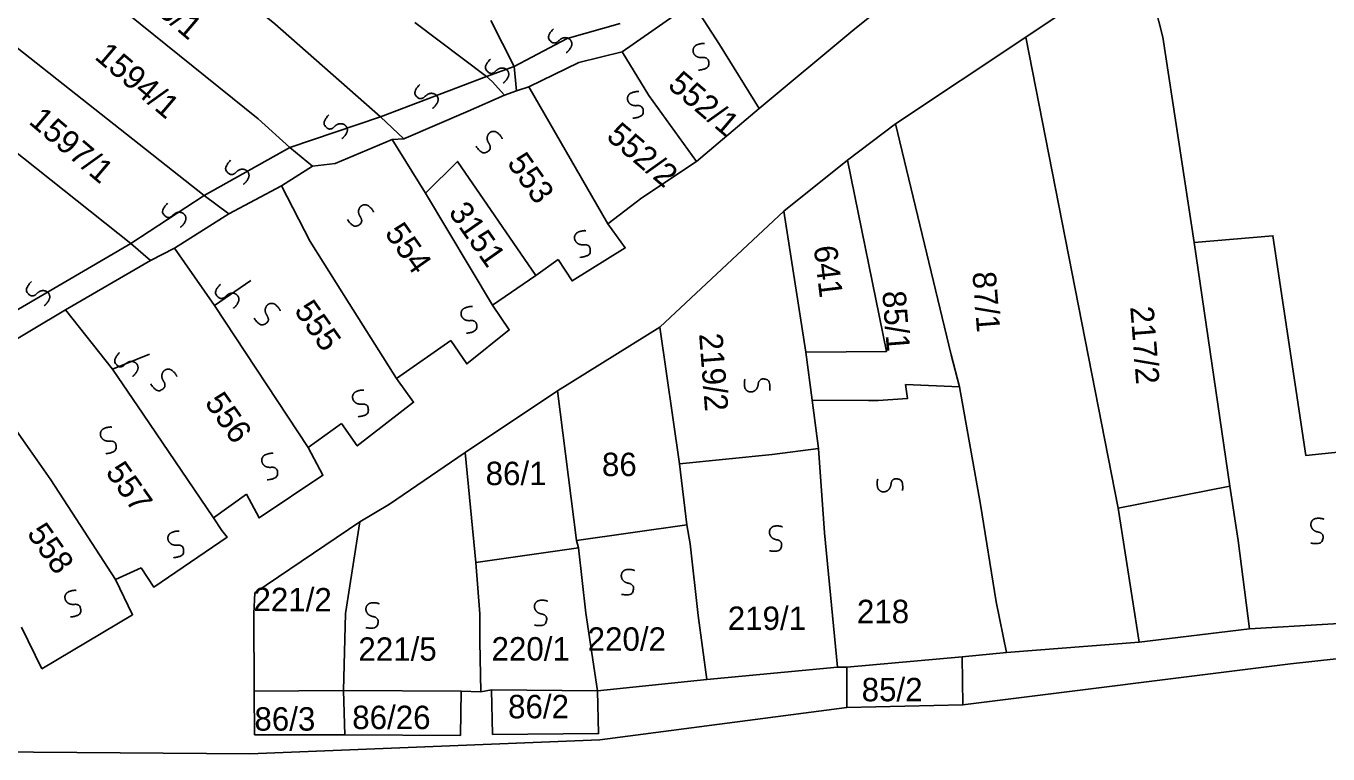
# Model space of a CAD drawing. Extents: x -581999 to -572728, y -1219553 to -1212032.
# Drawn here: x -578042.6 to -577931.4, y -1215726.9 to -1215664.7 of the extents above; entities that cross this region are included whole.
import ezdxf

# ---------------------------------------------------------------- set-up
doc = ezdxf.new("R2010")
doc.units = 0
for name, color, linetype in [('Vrstva 1', 7, 'Continuous'), ('Vrstva 2', 7, 'Continuous'), ('Vrstva 4', 7, 'Continuous'), ('Vrstva 6', 7, 'Continuous')]:
    doc.layers.add(name, color=color, linetype=linetype)

msp = doc.modelspace()

# ---------------------------------------------------------------- linework, layer by layer
at = {"layer": 'Vrstva 1'}
for p, q in [((-578000.916, -1215668.166), (-578002.908, -1215664.238)), ((-578009.426, -1215664.406), (-578003.287, -1215669.031)), ((-578000.724, -1215670.267), (-578000.916, -1215668.166)), ((-578003.287, -1215669.031), (-578002.816, -1215669.453)), ((-578002.816, -1215669.453), (-578001.768, -1215670.63)), ((-578001.768, -1215670.63), (-578000.724, -1215670.267)), ((-578000.724, -1215670.267), (-577999.68, -1215669.905)), ((-578011.58, -1215705.586), (-578014.107, -1215707.078)), ((-578015.499, -1215721.494), (-578023.147, -1215721.566)), ((-578005.509, -1215725.357), (-578005.466, -1215721.56))]:
    msp.add_line(p, q, dxfattribs=at)
for points in [[(-578010.347, -1215674.345), (-578012.339, -1215672.49), (-578021.393, -1215664.534), (-578035.16, -1215653.349)], [(-577962.568, -1215657.531), (-577971.99, -1215665.112)], [(-578039.598, -1215659.101), (-578022.818, -1215672.639), (-578020.097, -1215675.084), (-578018.175, -1215676.685)], [(-577947.207, -1215658.946), (-577957.198, -1215665.671)], [(-577945.486, -1215665.678), (-577947.207, -1215658.946)], [(-577991.691, -1215666.918), (-577985.695, -1215662.736)], [(-577983.381, -1215666.283), (-577985.695, -1215662.736)], [(-577979.987, -1215671.753), (-577971.99, -1215665.112)], [(-578044.482, -1215665.732), (-578027.425, -1215679.191), (-578025.299, -1215680.776)], [(-577979.987, -1215671.753), (-577983.381, -1215666.283)], [(-577957.198, -1215665.671), (-577968.344, -1215673.088)], [(-577949.308, -1215705.915), (-577957.198, -1215665.671)], [(-577942.813, -1215683.203), (-577945.486, -1215665.678)], [(-577995.412, -1215667.819), (-577991.691, -1215666.918)], [(-577989.416, -1215670.654), (-577991.691, -1215666.918)], [(-577999.68, -1215669.905), (-577995.412, -1215667.819)], [(-578004.855, -1215671.989), (-578001.768, -1215670.63)], [(-577992.91, -1215681.615), (-577999.68, -1215669.905)], [(-577985.349, -1215676.302), (-577989.416, -1215670.654)], [(-578032, -1215684.75), (-578033.675, -1215683.298), (-578048.595, -1215671.467)], [(-578010.347, -1215674.345), (-578004.855, -1215671.989)], [(-577985.349, -1215676.302), (-577979.987, -1215671.753)], [(-577968.344, -1215673.088), (-577972.433, -1215676.18)], [(-577963.579, -1215692.812), (-577968.344, -1215673.088)], [(-578016.228, -1215676.473), (-578011.355, -1215674.419)], [(-578011.355, -1215674.419), (-578010.347, -1215674.345)], [(-578008.5, -1215679.005), (-578011.355, -1215674.419)], [(-578018.175, -1215676.685), (-578016.228, -1215676.473)], [(-577999.067, -1215686.03), (-578005.782, -1215676.282), (-578008.5, -1215679.005)], [(-577990.023, -1215679.406), (-577985.349, -1215676.302)], [(-577972.433, -1215676.18), (-577977.884, -1215680.547)], [(-577976, -1215692.59), (-577969.108, -1215692.52), (-577972.433, -1215676.18)], [(-578018.175, -1215676.685), (-578020.806, -1215678.374)], [(-578020.806, -1215678.374), (-578025.299, -1215680.776)], [(-578018.367, -1215683.132), (-578020.806, -1215678.374)], [(-578002.791, -1215688.575), (-578008.5, -1215679.005)], [(-577992.91, -1215681.615), (-577990.023, -1215679.406)], [(-578029.957, -1215683.702), (-578025.299, -1215680.776)], [(-577977.884, -1215680.547), (-577988.492, -1215690.448)], [(-577976, -1215692.59), (-577977.884, -1215680.547)], [(-577997.158, -1215684.666), (-577995.983, -1215686.496), (-577991.442, -1215683.679), (-577992.91, -1215681.615)], [(-578015.023, -1215688.439), (-578018.367, -1215683.132)], [(-577939.786, -1215704.027), (-577942.813, -1215683.203)], [(-578032, -1215684.75), (-578029.957, -1215683.702)], [(-578026.544, -1215688.586), (-578029.957, -1215683.702)], [(-578039.258, -1215688.975), (-578032, -1215684.75)], [(-577999.067, -1215686.03), (-577997.158, -1215684.666)], [(-578002.791, -1215688.575), (-577999.067, -1215686.03)], [(-578018.542, -1215700.734), (-578026.544, -1215688.586)], [(-578010.969, -1215694.85), (-578015.023, -1215688.439)], [(-578006.335, -1215691.578), (-578004.979, -1215693.591), (-578001.344, -1215690.68), (-578002.791, -1215688.575)], [(-578045.109, -1215692.441), (-578039.258, -1215688.975)], [(-578035.266, -1215694.038), (-578039.258, -1215688.975)], [(-577988.492, -1215690.448), (-577997.211, -1215695.899)], [(-577986.792, -1215702.127), (-577988.492, -1215690.448)], [(-578010.969, -1215694.85), (-578006.335, -1215691.578)], [(-577975.466, -1215696.701), (-577976, -1215692.59)], [(-577962.86, -1215695.553), (-577963.579, -1215692.812)], [(-578042.318, -1215700.935), (-578047.168, -1215694.068)], [(-578032.643, -1215697.882), (-578035.266, -1215694.038)], [(-578015.694, -1215698.671), (-578014.338, -1215700.593), (-578009.522, -1215696.864), (-578010.969, -1215694.85)], [(-577962.86, -1215695.553), (-577967.483, -1215695.356), (-577967.306, -1215696.544), (-577969.827, -1215696.727), (-577970.244, -1215696.721)], [(-577997.211, -1215695.899), (-578005.115, -1215701.171)], [(-577995.605, -1215708.674), (-577997.211, -1215695.899)], [(-577961.073, -1215705.601), (-577962.86, -1215695.553)], [(-577974.932, -1215700.81), (-577975.466, -1215696.701)], [(-577970.244, -1215696.721), (-577970.66, -1215696.716), (-577975.466, -1215696.701)], [(-578026.629, -1215706.737), (-578032.643, -1215697.882)], [(-578018.542, -1215700.734), (-578015.694, -1215698.671)], [(-578038.343, -1215706.828), (-578040.509, -1215703.499), (-578042.318, -1215700.935)], [(-578023.813, -1215704.736), (-578022.729, -1215706.749), (-578017.278, -1215703.112), (-578018.542, -1215700.734)], [(-577978.87, -1215701.321), (-577974.932, -1215700.81)], [(-577974.406, -1215708.025), (-577974.932, -1215700.81)], [(-578005.115, -1215701.171), (-578011.58, -1215705.586)], [(-578004.213, -1215710.567), (-578005.115, -1215701.171)], [(-577986.792, -1215702.127), (-577978.87, -1215701.321)], [(-577986.171, -1215707.333), (-577986.792, -1215702.127)], [(-577949.308, -1215705.915), (-577939.786, -1215704.027)], [(-577939.074, -1215708.685), (-577939.786, -1215704.027)], [(-578026.629, -1215706.737), (-578023.813, -1215704.736)], [(-577959.734, -1215713.913), (-577961.073, -1215705.601)], [(-577947.517, -1215717.383), (-577949.308, -1215705.915)], [(-578034.986, -1215712.007), (-578038.343, -1215706.828)], [(-578032.808, -1215711.009), (-578031.723, -1215712.656), (-578025.453, -1215708.384), (-578025.906, -1215707.834), (-578026.629, -1215706.737)], [(-578014.107, -1215707.078), (-578023.101, -1215713.168), (-578023.187, -1215714.908)], [(-578014.107, -1215707.078), (-578015.337, -1215714.932)], [(-577986.171, -1215707.333), (-577995.605, -1215708.674)], [(-577985.902, -1215708.978), (-577986.171, -1215707.333)], [(-577995.605, -1215708.674), (-577995.425, -1215709.313)], [(-577973.308, -1215719.495), (-577974.406, -1215708.025)], [(-577938.087, -1215716.225), (-577939.074, -1215708.685)], [(-578004.213, -1215710.567), (-577995.425, -1215709.313)], [(-577995.425, -1215709.313), (-577995.114, -1215712.099)], [(-577985.191, -1215715.096), (-577985.902, -1215708.978)], [(-578034.986, -1215712.007), (-578032.808, -1215711.009)], [(-578003.861, -1215714.95), (-578004.213, -1215710.567)], [(-578041.283, -1215719.648), (-578033.542, -1215715.025), (-578034.986, -1215712.007)], [(-577995.114, -1215712.099), (-577994.803, -1215714.884)], [(-577958.849, -1215718.261), (-577959.734, -1215713.913)], [(-578023.187, -1215714.908), (-578023.147, -1215721.566), (-578023.105, -1215725.279)], [(-578015.499, -1215721.494), (-578015.337, -1215714.932)], [(-578003.785, -1215721.615), (-578003.856, -1215717.327), (-578003.861, -1215714.95)], [(-577994.803, -1215714.884), (-577993.803, -1215721.533)], [(-577984.462, -1215720.557), (-577985.191, -1215715.096)], [(-577938.087, -1215716.225), (-577924.713, -1215715.444), (-577913.836, -1215714.565)], [(-578043.041, -1215716.088), (-578041.283, -1215719.648)], [(-577947.517, -1215717.383), (-577938.087, -1215716.225)], [(-577962.577, -1215722.723), (-577934.59, -1215719.212), (-577918.452, -1215717.442)], [(-577958.849, -1215718.261), (-577947.517, -1215717.383)], [(-578126.538, -1215718.24), (-578119.18, -1215721.907), (-578097.504, -1215726.345), (-578023.529, -1215726.924)], [(-577962.658, -1215718.615), (-577972.491, -1215719.498)], [(-577962.658, -1215718.615), (-577958.849, -1215718.261)], [(-577962.577, -1215722.723), (-577962.658, -1215718.615)], [(-577984.462, -1215720.557), (-577973.308, -1215719.495)], [(-577973.308, -1215719.495), (-577972.491, -1215719.498)], [(-577972.491, -1215719.498), (-577972.5, -1215722.966)], [(-577993.803, -1215721.533), (-577984.462, -1215720.557)], [(-578015.395, -1215725.302), (-578015.499, -1215721.494)], [(-578015.499, -1215721.494), (-578005.466, -1215721.56)], [(-578005.466, -1215721.56), (-578003.785, -1215721.615)], [(-578002.878, -1215721.435), (-578003.785, -1215721.615)], [(-578002.789, -1215725.248), (-578002.878, -1215721.435)], [(-577993.803, -1215721.533), (-578002.878, -1215721.435)], [(-578002.789, -1215725.248), (-577993.721, -1215725.184), (-577993.803, -1215721.533)], [(-578023.529, -1215726.924), (-577993.614, -1215725.708), (-577972.5, -1215722.966)], [(-577972.5, -1215722.966), (-577962.577, -1215722.723)], [(-578023.105, -1215725.279), (-578015.395, -1215725.302)], [(-578015.395, -1215725.302), (-578005.509, -1215725.357)]]:
    msp.add_lwpolyline(points, dxfattribs=at)
at = {"layer": 'Vrstva 4'}
for p, q in [((-577996.39, -1215665.788), (-577991.864, -1215664.491)), ((-578000.916, -1215668.166), (-577996.39, -1215665.788)), ((-578003.287, -1215669.031), (-578000.916, -1215668.166)), ((-578012.339, -1215672.49), (-578003.287, -1215669.031)), ((-578020.097, -1215675.084), (-578012.339, -1215672.49)), ((-578027.425, -1215679.191), (-578020.097, -1215675.084)), ((-578033.675, -1215683.298), (-578027.425, -1215679.191)), ((-578047.037, -1215691.08), (-578033.675, -1215683.298))]:
    msp.add_line(p, q, dxfattribs=at)
for points in [[(-577942.813, -1215683.203), (-577936.092, -1215682.642), (-577933.264, -1215701.42), (-577919.032, -1215699.929), (-577918.88, -1215706.241)], [(-578023.438, -1215686.467), (-578026.544, -1215688.586)], [(-578032.1, -1215692.757), (-578035.266, -1215694.038)]]:
    msp.add_lwpolyline(points, dxfattribs=at)
at = {"layer": 'Vrstva 6'}
for points in [[(-577997.573, -1215664.943), (-577998.16, -1215665.565), (-577997.705, -1215666.174), (-577997.299, -1215666.162), (-577997.013, -1215665.857), (-577996.707, -1215665.703), (-577996.407, -1215665.719), (-577996.2, -1215665.821), (-577996.024, -1215666.024), (-577995.979, -1215666.388), (-577996.314, -1215666.9), (-577996.472, -1215666.992)], [(-577985.174, -1215668.487), (-577984.323, -1215668.398), (-577984.271, -1215667.64), (-577984.587, -1215667.384), (-577985.003, -1215667.429), (-577985.335, -1215667.347), (-577985.552, -1215667.139), (-577985.643, -1215666.927), (-577985.644, -1215666.658), (-577985.441, -1215666.353), (-577984.853, -1215666.183), (-577984.673, -1215666.216)], [(-578002.961, -1215667.537), (-578003.548, -1215668.159), (-578003.093, -1215668.768), (-578002.687, -1215668.756), (-578002.401, -1215668.451), (-578002.095, -1215668.297), (-578001.795, -1215668.313), (-578001.588, -1215668.415), (-578001.412, -1215668.618), (-578001.367, -1215668.982), (-578001.702, -1215669.494), (-578001.86, -1215669.586)], [(-578008.996, -1215669.699), (-578009.583, -1215670.321), (-578009.128, -1215670.93), (-578008.722, -1215670.918), (-578008.436, -1215670.613), (-578008.13, -1215670.459), (-578007.83, -1215670.475), (-578007.623, -1215670.577), (-578007.447, -1215670.78), (-578007.402, -1215671.144), (-578007.737, -1215671.656), (-578007.895, -1215671.748)], [(-577990.777, -1215672.595), (-577989.926, -1215672.506), (-577989.874, -1215671.748), (-577990.19, -1215671.492), (-577990.606, -1215671.537), (-577990.938, -1215671.455), (-577991.155, -1215671.247), (-577991.246, -1215671.035), (-577991.247, -1215670.766), (-577991.044, -1215670.461), (-577990.456, -1215670.291), (-577990.276, -1215670.324)], [(-578016.755, -1215672.293), (-578017.342, -1215672.915), (-578016.887, -1215673.524), (-578016.481, -1215673.512), (-578016.195, -1215673.207), (-578015.889, -1215673.053), (-578015.589, -1215673.069), (-578015.382, -1215673.171), (-578015.206, -1215673.374), (-578015.161, -1215673.738), (-578015.496, -1215674.25), (-578015.654, -1215674.342)], [(-578004.188, -1215674.984), (-578003.708, -1215675.691), (-578003.014, -1215675.38), (-578002.937, -1215674.98), (-578003.173, -1215674.635), (-578003.258, -1215674.303), (-578003.176, -1215674.013), (-578003.032, -1215673.833), (-578002.796, -1215673.705), (-578002.431, -1215673.741), (-578002.004, -1215674.18), (-578001.949, -1215674.353)], [(-578025.16, -1215676.184), (-578025.747, -1215676.806), (-578025.292, -1215677.415), (-578024.886, -1215677.403), (-578024.6, -1215677.098), (-578024.294, -1215676.944), (-578023.994, -1215676.96), (-578023.787, -1215677.062), (-578023.611, -1215677.265), (-578023.566, -1215677.629), (-578023.901, -1215678.141), (-578024.059, -1215678.233)], [(-578030.548, -1215679.858), (-578031.135, -1215680.48), (-578030.68, -1215681.089), (-578030.274, -1215681.077), (-578029.988, -1215680.772), (-578029.682, -1215680.618), (-578029.382, -1215680.634), (-578029.175, -1215680.736), (-578028.999, -1215680.939), (-578028.954, -1215681.303), (-578029.289, -1215681.815), (-578029.447, -1215681.907)], [(-578015.179, -1215681.253), (-578014.699, -1215681.96), (-578014.005, -1215681.649), (-578013.928, -1215681.249), (-578014.164, -1215680.904), (-578014.249, -1215680.572), (-578014.167, -1215680.282), (-578014.023, -1215680.102), (-578013.787, -1215679.974), (-578013.422, -1215680.01), (-578012.995, -1215680.449), (-578012.94, -1215680.622)], [(-577995.303, -1215684.484), (-577994.452, -1215684.395), (-577994.4, -1215683.637), (-577994.716, -1215683.381), (-577995.132, -1215683.426), (-577995.464, -1215683.344), (-577995.681, -1215683.136), (-577995.772, -1215682.924), (-577995.773, -1215682.655), (-577995.57, -1215682.35), (-577994.982, -1215682.18), (-577994.802, -1215682.213)], [(-578042.186, -1215686.559), (-578042.773, -1215687.181), (-578042.318, -1215687.79), (-578041.912, -1215687.778), (-578041.626, -1215687.473), (-578041.32, -1215687.319), (-578041.02, -1215687.335), (-578040.813, -1215687.437), (-578040.637, -1215687.64), (-578040.592, -1215688.004), (-578040.927, -1215688.516), (-578041.085, -1215688.608)], [(-578026.022, -1215686.775), (-578026.609, -1215687.397), (-578026.154, -1215688.006), (-578025.748, -1215687.994), (-578025.462, -1215687.689), (-578025.156, -1215687.535), (-578024.856, -1215687.551), (-578024.649, -1215687.653), (-578024.473, -1215687.856), (-578024.428, -1215688.22), (-578024.763, -1215688.732), (-578024.921, -1215688.824)], [(-578023.154, -1215689.683), (-578022.674, -1215690.39), (-578021.98, -1215690.079), (-578021.903, -1215689.679), (-578022.139, -1215689.334), (-578022.224, -1215689.002), (-578022.142, -1215688.712), (-578021.998, -1215688.532), (-578021.762, -1215688.404), (-578021.397, -1215688.44), (-578020.97, -1215688.879), (-578020.915, -1215689.052)], [(-578005.001, -1215690.969), (-578004.15, -1215690.88), (-578004.098, -1215690.122), (-578004.414, -1215689.866), (-578004.83, -1215689.911), (-578005.162, -1215689.829), (-578005.379, -1215689.621), (-578005.47, -1215689.409), (-578005.471, -1215689.14), (-578005.268, -1215688.835), (-578004.68, -1215688.665), (-578004.5, -1215688.698)], [(-578034.643, -1215692.612), (-578035.23, -1215693.234), (-578034.775, -1215693.843), (-578034.369, -1215693.831), (-578034.083, -1215693.526), (-578033.777, -1215693.372), (-578033.477, -1215693.388), (-578033.27, -1215693.49), (-578033.094, -1215693.693), (-578033.049, -1215694.057), (-578033.384, -1215694.569), (-578033.542, -1215694.661)], [(-578031.99, -1215695.304), (-578031.51, -1215696.011), (-578030.816, -1215695.7), (-578030.739, -1215695.3), (-578030.975, -1215694.955), (-578031.06, -1215694.623), (-578030.978, -1215694.333), (-578030.834, -1215694.153), (-578030.598, -1215694.025), (-578030.233, -1215694.061), (-578029.806, -1215694.5), (-578029.751, -1215694.673)], [(-577979.09, -1215695.877), (-577978.995, -1215695.026), (-577979.725, -1215694.814), (-577980.042, -1215695.068), (-577980.087, -1215695.484), (-577980.238, -1215695.791), (-577980.487, -1215695.958), (-577980.714, -1215696.002), (-577980.977, -1215695.946), (-577981.232, -1215695.682), (-577981.272, -1215695.072), (-577981.202, -1215694.903)], [(-578014.269, -1215698.102), (-578013.418, -1215698.013), (-578013.366, -1215697.255), (-578013.682, -1215696.999), (-578014.098, -1215697.044), (-578014.43, -1215696.962), (-578014.647, -1215696.754), (-578014.738, -1215696.542), (-578014.739, -1215696.273), (-578014.536, -1215695.968), (-578013.948, -1215695.798), (-578013.768, -1215695.831)], [(-578035.821, -1215701.262), (-578034.97, -1215701.173), (-578034.918, -1215700.415), (-578035.234, -1215700.159), (-578035.65, -1215700.204), (-578035.982, -1215700.122), (-578036.199, -1215699.914), (-578036.29, -1215699.702), (-578036.291, -1215699.433), (-578036.088, -1215699.128), (-578035.5, -1215698.958), (-578035.32, -1215698.991)], [(-578022.027, -1215703.506), (-578021.176, -1215703.417), (-578021.124, -1215702.659), (-578021.44, -1215702.403), (-578021.856, -1215702.448), (-578022.188, -1215702.366), (-578022.405, -1215702.158), (-578022.496, -1215701.946), (-578022.497, -1215701.677), (-578022.294, -1215701.372), (-578021.706, -1215701.202), (-578021.526, -1215701.235)], [(-577967.742, -1215704.414), (-577967.647, -1215703.563), (-577968.377, -1215703.351), (-577968.694, -1215703.605), (-577968.739, -1215704.021), (-577968.89, -1215704.328), (-577969.139, -1215704.495), (-577969.366, -1215704.539), (-577969.629, -1215704.483), (-577969.884, -1215704.219), (-577969.924, -1215703.609), (-577969.854, -1215703.44)], [(-577979.111, -1215709.562), (-577978.27, -1215709.714), (-577978.007, -1215709), (-577978.239, -1215708.666), (-577978.651, -1215708.593), (-577978.947, -1215708.421), (-577979.097, -1215708.16), (-577979.125, -1215707.931), (-577979.051, -1215707.673), (-577978.77, -1215707.437), (-577978.158, -1215707.439), (-577977.995, -1215707.521)], [(-577932.843, -1215708.905), (-577932.002, -1215709.057), (-577931.739, -1215708.343), (-577931.971, -1215708.009), (-577932.383, -1215707.936), (-577932.679, -1215707.764), (-577932.829, -1215707.503), (-577932.857, -1215707.274), (-577932.783, -1215707.016), (-577932.502, -1215706.78), (-577931.89, -1215706.782), (-577931.727, -1215706.864)], [(-578030.053, -1215710.156), (-578029.202, -1215710.067), (-578029.15, -1215709.309), (-578029.466, -1215709.053), (-578029.882, -1215709.098), (-578030.214, -1215709.016), (-578030.431, -1215708.808), (-578030.522, -1215708.596), (-578030.523, -1215708.327), (-578030.32, -1215708.022), (-578029.732, -1215707.852), (-578029.552, -1215707.885)], [(-577991.769, -1215713.283), (-577990.928, -1215713.435), (-577990.665, -1215712.721), (-577990.897, -1215712.387), (-577991.309, -1215712.314), (-577991.605, -1215712.142), (-577991.755, -1215711.881), (-577991.783, -1215711.652), (-577991.709, -1215711.394), (-577991.428, -1215711.158), (-577990.816, -1215711.16), (-577990.653, -1215711.242)], [(-578038.849, -1215715.218), (-578037.998, -1215715.129), (-578037.946, -1215714.371), (-578038.262, -1215714.115), (-578038.678, -1215714.16), (-578039.01, -1215714.078), (-578039.227, -1215713.87), (-578039.318, -1215713.658), (-578039.319, -1215713.389), (-578039.116, -1215713.084), (-578038.528, -1215712.914), (-578038.348, -1215712.947)], [(-578013.594, -1215716.129), (-578012.753, -1215716.281), (-578012.49, -1215715.567), (-578012.722, -1215715.233), (-578013.134, -1215715.16), (-578013.43, -1215714.988), (-578013.58, -1215714.727), (-578013.608, -1215714.498), (-578013.534, -1215714.24), (-578013.253, -1215714.004), (-578012.641, -1215714.006), (-578012.478, -1215714.088)], [(-577999.19, -1215715.91), (-577998.349, -1215716.062), (-577998.086, -1215715.348), (-577998.318, -1215715.014), (-577998.73, -1215714.941), (-577999.026, -1215714.769), (-577999.176, -1215714.508), (-577999.204, -1215714.279), (-577999.13, -1215714.021), (-577998.849, -1215713.785), (-577998.237, -1215713.787), (-577998.074, -1215713.869)]]:
    msp.add_open_spline(points, degree=2, dxfattribs=at)

# ---------------------------------------------------------------- texts
at = {"layer": 'Vrstva 2'}
for s, rotation, p in [('1593/1', 319.61095, (-578034.934, -1215660.704)), ('1594/1', 319.61095, (-578036.868, -1215667.456)), ('552/1', 319.61095, (-577987.902, -1215669.917)), ('1597/1', 319.61095, (-578042.499, -1215672.987)), ('552/2', 319.61095, (-577993.149, -1215674.299)), ('553', 305.146, (-578001.595, -1215676.43)), ('3151', 305.146, (-578006.601, -1215680.633)), ('554', 305.146, (-578012.052, -1215682.419)), ('641', 276.91315, (-577975.34, -1215683.579)), ('87/1', 274.46462, (-577961.774, -1215685.764)), ('85/1', 274.46462, (-577969.475, -1215687.411)), ('555', 305.146, (-578019.786, -1215689.039)), ('217/2', 274.46462, (-577948.287, -1215688.722)), ('219/2', 274.46462, (-577985.131, -1215691.034)), ('556', 305.146, (-578027.432, -1215696.907)), ('557', 305.146, (-578035.908, -1215702.838)), ('558', 305.146, (-578042.628, -1215708.083)), ('221/2', 359.6864, (-578023.211, -1215714.711))]:
    msp.add_text(s, height=2, rotation=rotation, dxfattribs=at).set_placement(p)
for s, p in [('86/1', (-578003.366, -1215703.95)), ('86', (-577993.428, -1215703.178)), ('219/1', (-577982.676, -1215716.325)), ('218', (-577971.639, -1215715.747)), ('220/2', (-577994.648, -1215718.103)), ('221/5', (-578014.24, -1215718.962)), ('220/1', (-578002.861, -1215718.939)), ('85/2', (-577971.235, -1215722.423)), ('86/2', (-578001.447, -1215723.876)), ('86/3', (-578023.124, -1215724.931)), ('86/26', (-578014.765, -1215724.799))]:
    msp.add_text(s, height=2, dxfattribs=at).set_placement(p)

doc.saveas('drawing.dxf')
